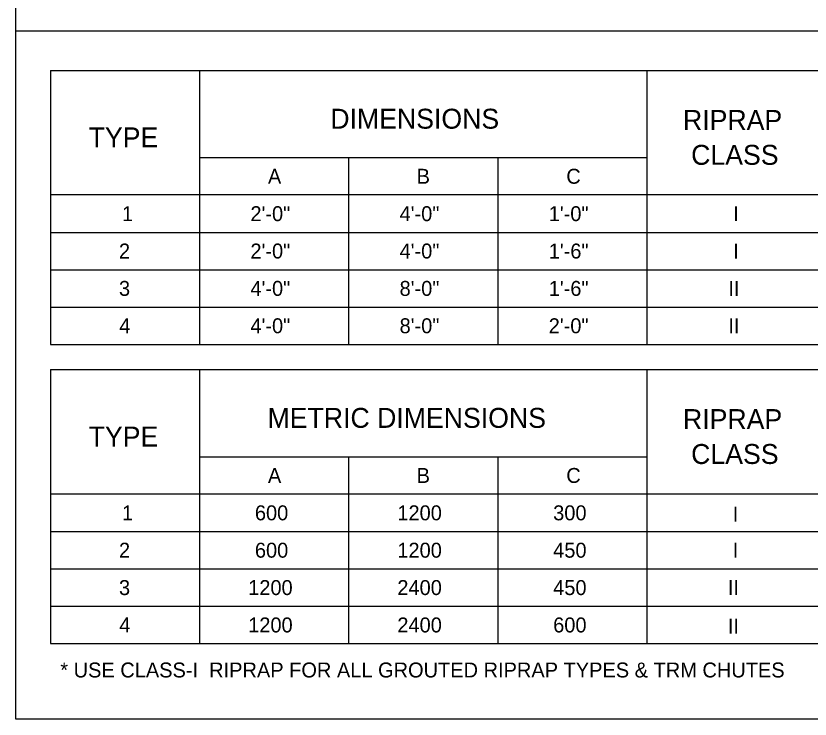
# Model space of a CAD drawing. Extents: x 49991.4 to 50021, y 49987.6 to 50011.4.
# Drawn here: x 49999.384 to 50002.571, y 49987.799 to 49990.622 of the extents above; entities that cross this region are included whole.
import ezdxf

# ---------------------------------------------------------------- set-up
doc = ezdxf.new("R2010")
doc.units = 0
doc.layers.add('Level 1', color=7, linetype='Continuous')
doc.layers.add('Level 2', color=7, linetype='Continuous')

msp = doc.modelspace()

# ---------------------------------------------------------------- linework, layer by layer
at = {"layer": 'Level 1'}
msp.add_line((49999.3835, 49990.5622), (50016.7501, 49990.5622), dxfattribs=at)
msp.add_lwpolyline([(49999.3835, 49998.9992), (50016.7501, 49998.9992), (50016.7501, 49987.7988), (49999.3835, 49987.7988)], close=True, dxfattribs=at)
at = {"layer": 'Level 2'}
for p, q in [((49999.523, 49990.4027), (50010.5707, 49990.4027)), ((49999.523, 49990.4027), (49999.523, 49989.3027)), ((50000.1215, 49989.3027), (50000.1215, 49990.4027)), ((50001.917, 49989.3027), (50001.917, 49990.4027)), ((50000.1215, 49990.0527), (50001.917, 49990.0527)), ((50000.72, 49989.3027), (50000.72, 49990.0527)), ((50001.3185, 49989.3027), (50001.3185, 49990.0527)), ((50002.6362, 49989.9027), (49999.523, 49989.9027)), ((49999.523, 49989.7527), (50007.6678, 49989.7527)), ((49999.523, 49989.6027), (50007.6678, 49989.6027)), ((49999.523, 49989.4527), (50007.6678, 49989.4527)), ((49999.523, 49989.3027), (50007.6678, 49989.3027)), ((49999.523, 49989.2018), (50010.5707, 49989.2018)), ((49999.523, 49989.2018), (49999.523, 49988.1018)), ((50000.1215, 49988.1018), (50000.1215, 49989.2018)), ((50001.917, 49988.1018), (50001.917, 49989.2018)), ((50000.1215, 49988.8518), (50001.917, 49988.8518)), ((50000.72, 49988.1018), (50000.72, 49988.8518)), ((50001.3185, 49988.1018), (50001.3185, 49988.8518)), ((50002.6362, 49988.7018), (49999.523, 49988.7018)), ((49999.523, 49988.5518), (50007.6678, 49988.5518)), ((49999.523, 49988.4018), (50007.6678, 49988.4018)), ((49999.523, 49988.2518), (50007.6678, 49988.2518)), ((49999.523, 49988.1018), (50010.5707, 49988.1018)), ((49999.523, 49988.1018), (50007.6678, 49988.1018))]:
    msp.add_line(p, q, dxfattribs=at)

# ---------------------------------------------------------------- texts
for s, height, p in [('DIMENSIONS', 0.08, (50000.6453, 49990.1688)), ('RIPRAP', 0.08, (50002.0605, 49990.1638)), ('TYPE', 0.08, (49999.6755, 49990.0938)), ('CLASS', 0.08, (50002.0933, 49990.0238)), ('A', 0.06, (50000.395, 49989.9477)), ('B', 0.06, (50000.9917, 49989.9477)), ('C', 0.06, (50001.5923, 49989.9477)), ('1', 0.06, (49999.8094, 49989.7977)), ('2\'-0"', 0.06, (50000.3247, 49989.7977)), ('4\'-0"', 0.06, (50000.9233, 49989.7977)), ('1\'-0"', 0.06, (50001.5217, 49989.7977)), ('I', 0.06, (50002.2622, 49989.7977)), ('2', 0.06, (49999.7972, 49989.6477)), ('2\'-0"', 0.06, (50000.3247, 49989.6477)), ('4\'-0"', 0.06, (50000.9233, 49989.6477)), ('1\'-6"', 0.06, (50001.5217, 49989.6477)), ('I', 0.06, (50002.2622, 49989.6477)), ('3', 0.06, (49999.7972, 49989.4977)), ('4\'-0"', 0.06, (50000.3247, 49989.4977)), ('8\'-0"', 0.06, (50000.9233, 49989.4977)), ('1\'-6"', 0.06, (50001.5217, 49989.4977)), ('II', 0.06, (50002.2428, 49989.4977)), ('4', 0.06, (49999.7984, 49989.3477)), ('4\'-0"', 0.06, (50000.3247, 49989.3477)), ('8\'-0"', 0.06, (50000.9233, 49989.3477)), ('2\'-0"', 0.06, (50001.5217, 49989.3477)), ('II', 0.06, (50002.2428, 49989.3477)), ('METRIC DIMENSIONS', 0.08, (50000.3933, 49988.968)), ('RIPRAP', 0.08, (50002.0605, 49988.963)), ('TYPE', 0.08, (49999.6755, 49988.893)), ('CLASS', 0.08, (50002.0933, 49988.823)), ('A', 0.06, (50000.395, 49988.7468)), ('B', 0.06, (50000.9917, 49988.7468)), ('C', 0.06, (50001.5923, 49988.7468)), ('1', 0.06, (49999.8094, 49988.5968)), ('600', 0.06, (50000.3426, 49988.5968)), ('1200', 0.06, (50000.9143, 49988.5968)), ('300', 0.06, (50001.5396, 49988.5968)), ('I', 0.06, (50002.2599, 49988.591)), ('2', 0.06, (49999.7972, 49988.4468)), ('600', 0.06, (50000.3426, 49988.4468)), ('1200', 0.06, (50000.9143, 49988.4468)), ('450', 0.06, (50001.5396, 49988.4468)), ('I', 0.06, (50002.2599, 49988.4468)), ('3', 0.06, (49999.7972, 49988.2968)), ('1200', 0.06, (50000.3157, 49988.2968)), ('2400', 0.06, (50000.9143, 49988.2968)), ('450', 0.06, (50001.5396, 49988.2968)), ('II', 0.06, (50002.2405, 49988.2968)), ('4', 0.06, (49999.7984, 49988.1468)), ('1200', 0.06, (50000.3157, 49988.1468)), ('2400', 0.06, (50000.9143, 49988.1468)), ('600', 0.06, (50001.5396, 49988.1468)), ('II', 0.06, (50002.2405, 49988.1419)), ('* USE CLASS-I  RIPRAP FOR ALL GROUTED RIPRAP TYPES & TRM CHUTES', 0.06, (49999.5617, 49987.966))]:
    msp.add_text(s, height=height, dxfattribs=at).set_placement(p)

doc.saveas('drawing.dxf')
